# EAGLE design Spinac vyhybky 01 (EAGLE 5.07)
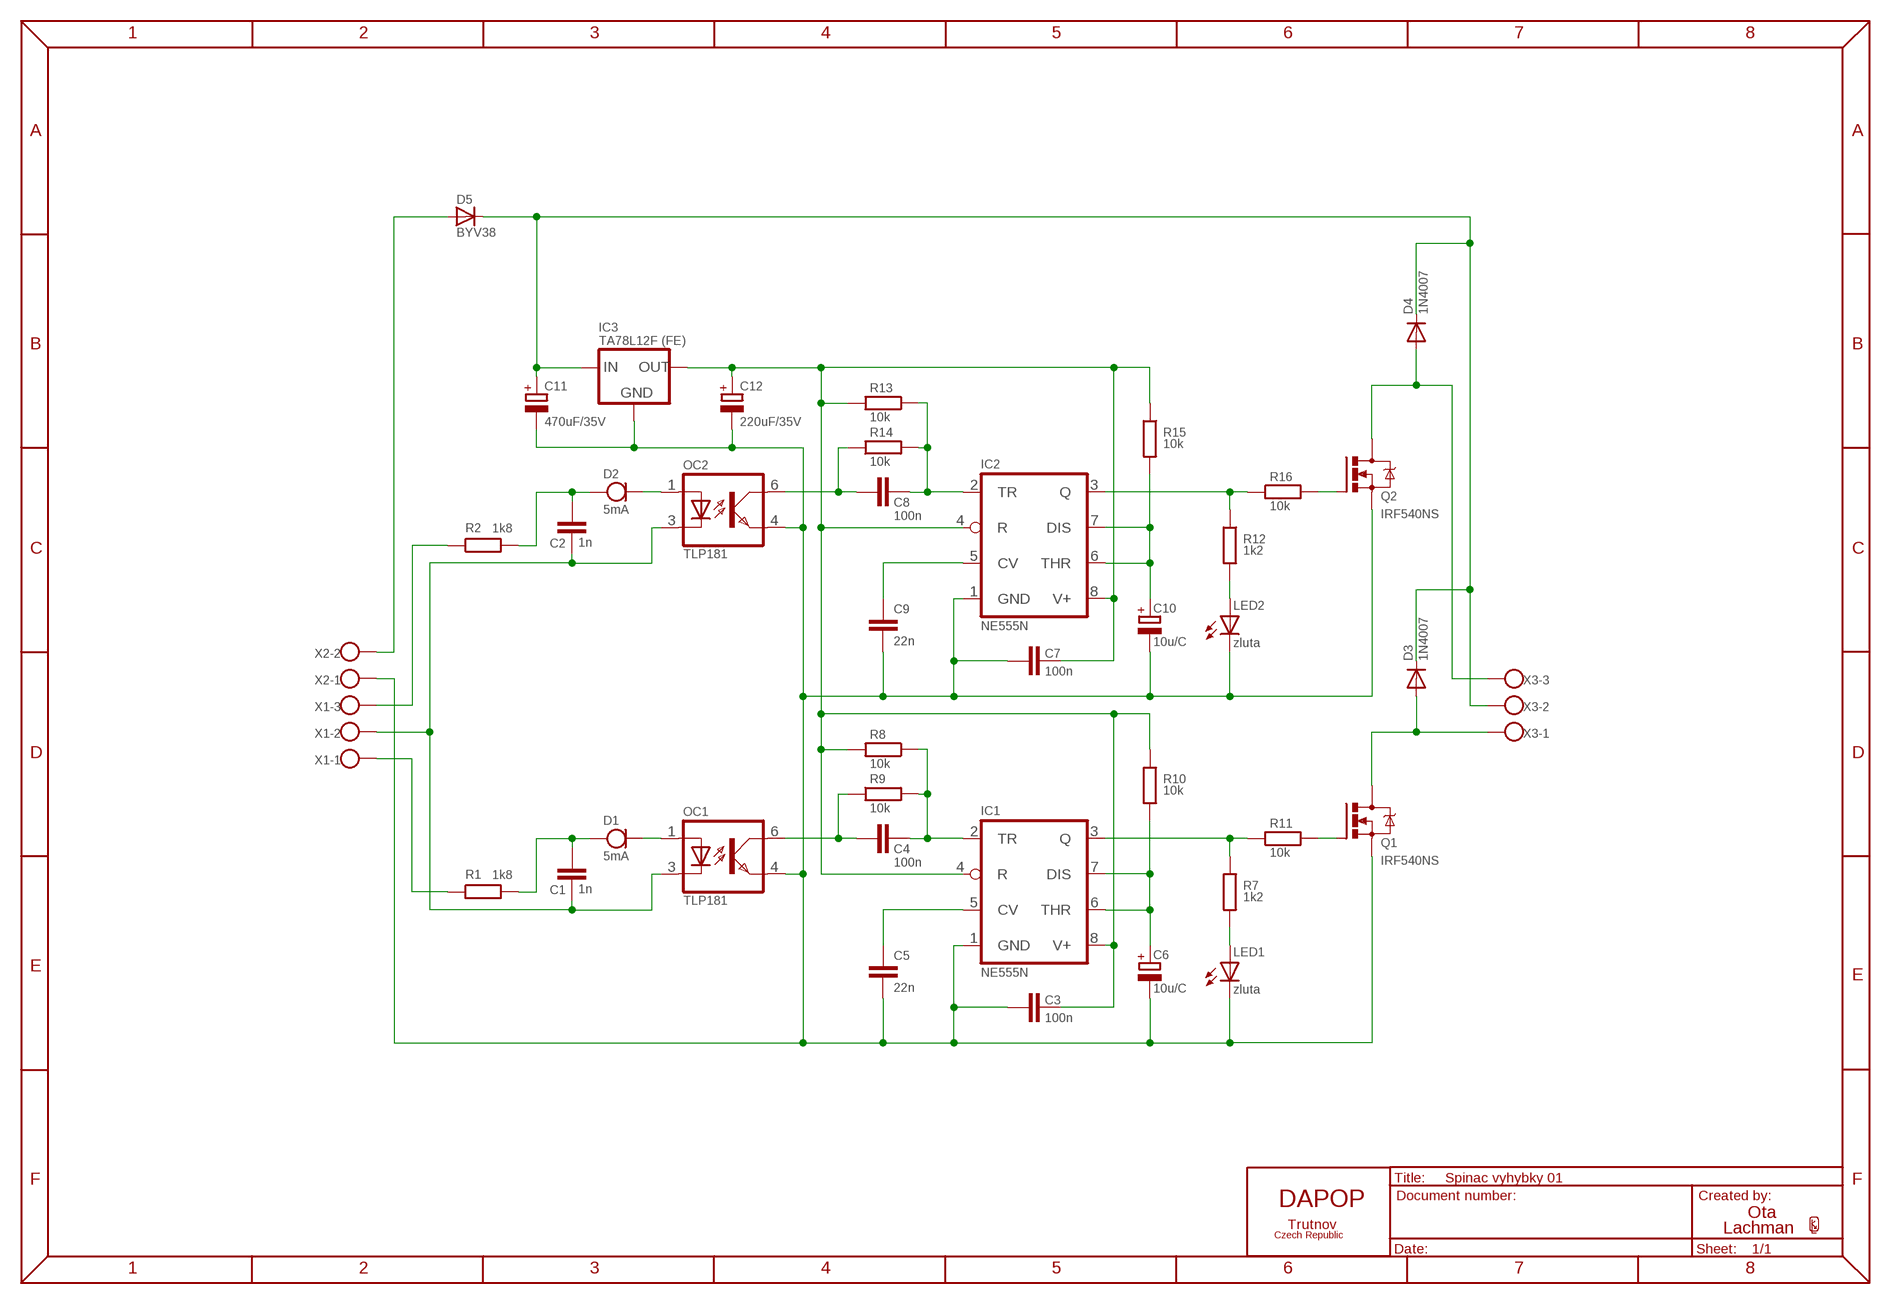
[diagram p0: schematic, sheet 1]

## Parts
C1  1n  C-EUC0805K  [C0805K]
C2  1n  C-EUC0805K  [C0805K]
C3  100n  C-EUC1206  [C1206]
C4  100n  C-EUC1206  [C1206]
C5  22n  C-EUC1206  [C1206]
C6  10u/C  CPOL-EUD/7343-31R  [D/7343-31R]
C7  100n  C-EUC1206  [C1206]
C8  100n  C-EUC1206  [C1206]
C9  22n  C-EUC1206  [C1206]
C10  10u/C  CPOL-EUD/7343-31R  [D/7343-31R]
C11  470uF/35V  CPOL-EUE5-10.5  [E5-10,5]
C12  220uF/35V  CPOL-EUE5-10.5  [E5-10,5]
D1  5mA  CRD-F  [MINIMELF]
D2  5mA  CRD-F  [MINIMELF]
D3  1N4007  DIODE-MINIMELF  [MINIMELF]
D4  1N4007  DIODE-MINIMELF  [MINIMELF]
D5  BYV38  [SOD57-10]
IC1  NE555N  [DIL08]
IC2  NE555N  [DIL08]
IC3  TA78L12F (FE)  TA78LXXF  [SOT89]
LED1  zluta  LED3MM  [LED3MM]
LED2  zluta  LED3MM  [LED3MM]
OC1  TLP181  [11-4C1]
OC2  TLP181  [11-4C1]
OL1  NAME-OL  [NAME-OL]
Q1  IRF540NS  [D2PACK]
Q2  IRF540NS  [D2PACK]
R1  1k8  R-EU_R1206  [R1206]
R2  1k8  R-EU_R1206  [R1206]
R7  1k2  R-EU_R0805  [R0805]
R8  10k  R-EU_R0805  [R0805]
R9  10k  R-EU_R0805  [R0805]
R10  10k  R-EU_R0805  [R0805]
R11  10k  R-EU_R0805  [R0805]
R12  1k2  R-EU_R0805  [R0805]
R13  10k  R-EU_R0805  [R0805]
R14  10k  R-EU_R0805  [R0805]
R15  10k  R-EU_R0805  [R0805]
R16  10k  R-EU_R0805  [R0805]
X1  AK500/3  [AK500/3]
X2  AK500/2  [AK500/2]
X3  AK500/3  [AK500/3]

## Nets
N$1: D2.C(K) OC2.1(A)
N$2: C1.2 C2.2 OC1.3(C) OC2.3(C) X1.2
N$3: C2.1 D2.A R2.2
N$4: R2.1 X1.3
N$5: C3.1 C5.2 C6.- C7.1 C9.2 C10.- C11.- C12.- IC1.1(GND) IC2.1(GND) IC3.2(GND) LED1.K(C) LED2.K(C) OC1.4(EMIT) OC2.4(EMIT) Q1.3(S) Q2.3(S) X2.1
N$6: C11.+ D3.C D4.C D5.C IC3.3(IN) X3.2
N$7: IC1.3(Q) R7.1 R11.1
N$8: LED1.A R7.2
N$9: C4.1 IC1.2(TR) R8.1 R9.2
N$10: C3.2 C7.2 C12.+ IC1.4(R) IC1.8(V+) IC2.4(R) IC2.8(V+) IC3.1(OUT) R8.2 R10.1 R13.2 R15.1
N$11: C4.2 OC1.6(COL) R9.1
N$12: C5.1 IC1.5(CV)
N$13: C6.+ IC1.6(THR) IC1.7(DIS) R10.2
N$14: D5.A X2.2
N$16: C1.1 D1.A R1.2
N$17: D1.C(K) OC1.1(A)
N$18: Q1.1(G) R11.2
N$19: IC2.3(Q) R12.1 R16.1
N$20: LED2.A R12.2
N$21: C8.1 IC2.2(TR) R13.1 R14.2
N$22: Q2.1(G) R16.2
N$23: C8.2 OC2.6(COL) R14.1
N$24: C9.1 IC2.5(CV)
N$25: C10.+ IC2.6(THR) IC2.7(DIS) R15.2
N$26: D4.A Q2.2(D) X3.3
N$27: D3.A Q1.2(D) X3.1
N$66: R1.1 X1.1

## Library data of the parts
C1-C5 C7-C9 = rcl:C-EU: CAPACITOR, European symbol
C6 C10-C12 = rcl:CPOL-EU: POLARIZED CAPACITOR, European symbol
D1 D2 = diode:CRD-F: CURRENT REGULATIVE DIODE
D3 D4 = diode:DIODE-: DIODE
D5 = diode:BYV38: DIODE
IC1 IC2 = linear:*555: TIMER
IC3 = v-reg:TA78LXXF: VOLTAGE REGULATOR
LED1 LED2 = led:LED: LED
OC1 OC2 = optocoupler:TLP181: TOSHIBA MINI FLAT OPTO COUPLER
OL1 = Names-And-Logos:NAME-OL: Name.
Q1 Q2 = transistor-power:IRF540*: HEXFET Power MOSFET
R1 R2 R7-R16 = rcl:R-EU_: RESISTOR, European symbol
X1 X3 = con-ptr500+:AK500/3: CONNECTOR
X2 = con-ptr500+:AK500/2: CONNECTOR

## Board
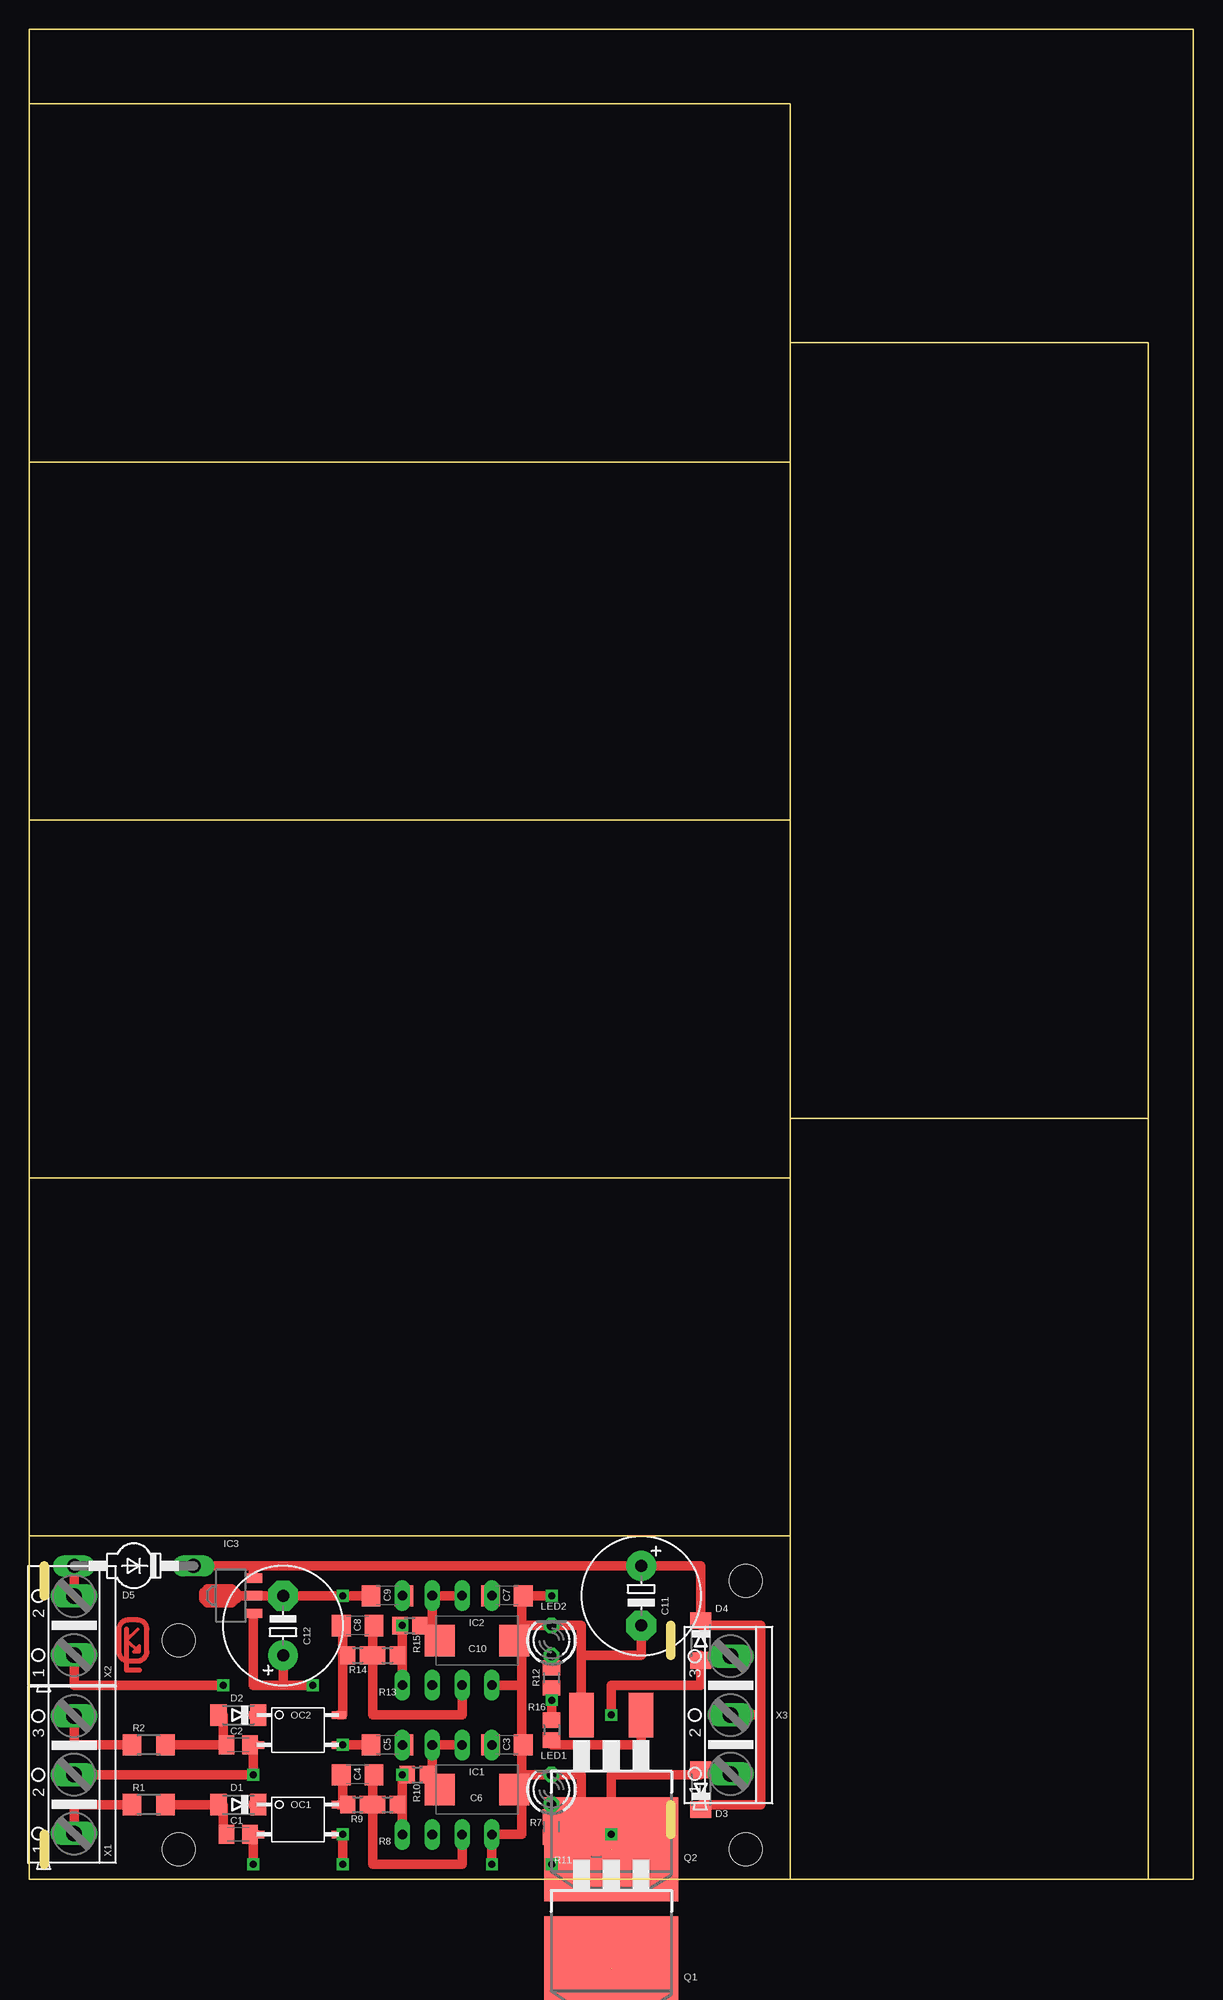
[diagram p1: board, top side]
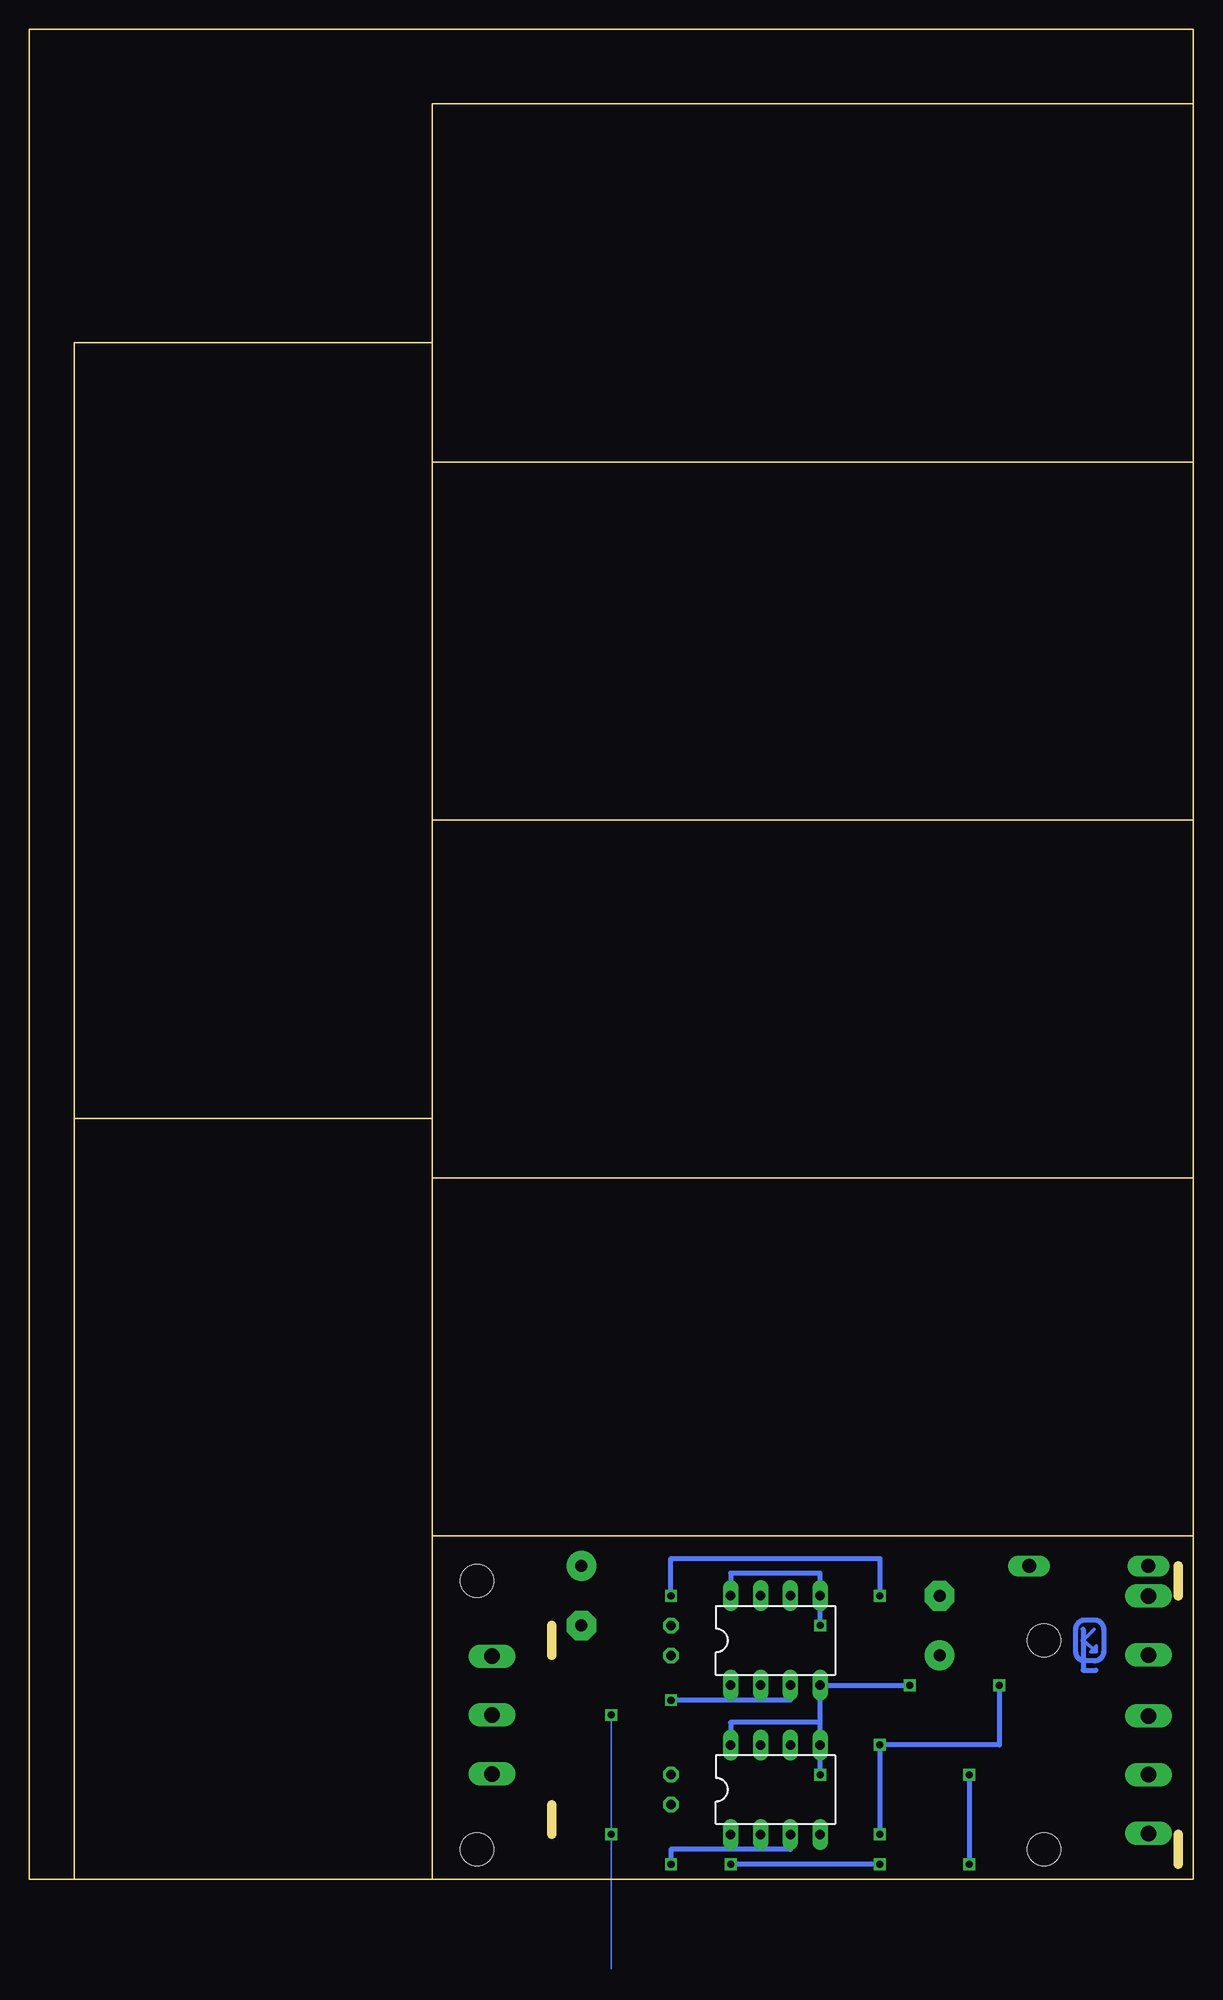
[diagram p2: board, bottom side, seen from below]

Size 99.06 x 157.48 mm. Coordinates in mm from the lower left corner, seen from the top.
Outline: 0,29.21 64.77,29.21
Outline: 64.77,29.21 64.77,0
Outline: 64.77,59.69 64.77,29.21
Outline: 0,59.69 64.77,59.69
Outline: 64.77,90.17 64.77,64.77
Outline: 64.77,64.77 64.77,59.69
Outline: 0,90.17 64.77,90.17
Outline: 64.77,120.65 64.77,90.17
Outline: 0,120.65 64.77,120.65
Outline: 64.77,130.81 64.77,151.13 0,151.13
Outline: 64.77,130.81 64.77,120.65
Outline: 64.77,64.77 95.25,64.77
Outline: 95.25,0 95.25,64.77
Outline: 95.25,64.77 95.25,130.81 64.77,130.81
Copper layers (1*16): Top 0.035mm / dielectric 1.5mm / Bottom 0.035mm
Design rules "default": minimum track width 10mil, minimum drill 24mil, track to track 8mil, track to pad 8mil, pad to pad 8mil, via to via 8mil, smd to smd 8mil, copper to edge 40mil, drill to drill 8mil, minimum pad ring 10mil, minimum via ring 8mil, stop-mask expansion 4mil, vias tented up to drill 0mil, thermal gap 10mil
Holes 2.8 mm at 12.7,2.54 60.96,2.54 60.96,25.4 12.7,20.32
Milling: 4 lines

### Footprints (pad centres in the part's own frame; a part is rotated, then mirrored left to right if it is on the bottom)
C0805K = smd 1.3 x 1.6: 1 -1,0; 2 1,0
C1206 = smd 1.6 x 1.8: 1 -1.4,0; 2 1.4,0
D/7343-31R = smd 2.55 x 2.7: + 3.175,0; - -3.175,0
E5-10,5 = drill 1.016 pad 2.54 round: + -2.54,0 | drill 1.016 pad 2.54 octagon: - 2.54,0
MINIMELF = smd 1.4 x 1.8: A 1.7,0; C -1.7,0
SOD57-10 = drill 1.194 long: A 5.08,0; C -5.08,0
DIL08 = drill 0.813 long: 1 -3.81,-3.81; 2 -1.27,-3.81; 3 1.27,-3.81; 4 3.81,-3.81; 5 3.81,3.81; 6 1.27,3.81; 7 -1.27,3.81; 8 -3.81,3.81
SOT89 = smd 0.8 x 1.4: 1 -1.499,-1.981; 2 0,-1.981; 3 1.499,-1.981
LED3MM = drill 0.813 octagon: A -1.27,0; K 1.27,0
11-4C1 = smd 1.27 x 0.635: 1 -3.493,1.27; 3 -3.493,-1.27; 4 3.493,-1.27; 6 3.493,1.27
D2PACK = smd 2.083 x 3.81: 1 -2.54,-8.89; 3 2.54,-8.89 | smd 11.43 x 8.89: 2 0,2.54
R1206 = smd 1.6 x 1.803: 1 -1.422,0; 2 1.422,0
R0805 = smd 1.3 x 1.5: 1 -0.85,0; 2 0.85,0
AK500/3 = drill 1.321 long: 1 -5.004,0; 2 0,0; 3 5.004,0
AK500/2 = drill 1.321 long: 1 -2.515,0; 2 2.515,0

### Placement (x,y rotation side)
C1  17.78,3.81 0 top
C2  17.78,11.43 0 top
C3  40.64,11.43 180 top
C4  27.94,8.89 180 top
C5  30.48,11.43 180 top
C6  38.1,7.62 180 top
C7  40.64,24.13 180 top
C8  27.94,21.59 180 top
C9  30.48,24.13 180 top
C10  38.1,20.32 180 top
C11  52.07,24.13 270 top
C12  21.59,21.59 90 top
D1  17.78,6.35 180 top
D2  17.78,13.97 180 top
D3  57.15,7.62 90 top
D4  57.15,20.32 270 top
D5  8.89,26.67 180 top
IC1  35.56,7.62 0 bottom
IC2  35.56,20.32 0 bottom
IC3  17.14,24.13 90 top
LED1  44.45,7.62 90 top
LED2  44.45,20.32 90 top
OC1  22.86,5.08 0 top
OC2  22.86,12.7 0 top
OL1  8.89,20.32 0 top
Q1  49.53,-5.08 180 top
Q2  49.53,5.08 180 top
R1  10.16,6.35 0 top
R2  10.16,11.43 0 top
R7  44.45,4.45 90 top
R8  30.48,6.35 0 top
R9  27.94,6.35 0 top
R10  33.02,8.89 0 top
R11  48.26,1.27 0 top
R12  44.45,17.14 90 top
R13  30.48,19.05 0 top
R14  27.94,19.05 0 top
R15  32.38,21.59 0 top
R16  44.45,12.7 270 top
U$2  [PAD02TOP]  99.06,0 90 top
X1  3.81,8.89 90 top
X2  3.81,21.59 90 top
X3  59.69,13.97 90 top

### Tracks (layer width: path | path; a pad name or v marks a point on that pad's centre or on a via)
N$1
  Top 0.813: D2.C OC2.1 19.05,13.97
N$2  (via drill 0.6)
  Top 0.813: 19.05,3.81 C1.2 | v19.05,1.27 19.05,3.81 | 19.05,3.81 OC1.3 | 19.05,11.43 v19.05,8.89 X1.2 | 19.05,11.43 C2.2 | 19.05,11.43 OC2.3
  Bottom 0.406: v19.05,8.89 v19.05,1.27
N$3
  Top 0.813: D2.A 16.51,13.97 16.51,11.43 | 16.51,11.43 C2.1 | R2.2 16.51,11.43
N$4
  Top 0.813: R2.1 3.81,11.43 3.81,13.97
N$5  (via drill 0.6)
  Top 0.813: v16.51,16.51 3.81,16.51 X2.1 | 16.51,24.13 IC3.2 C12.- v26.67,24.13 C9.2 29.21,24.13 | 46.99,19.05 Q2.3 | OC1.4 v26.67,3.81 v26.67,1.27 | OC2.4 v26.67,11.43 C5.2 29.21,11.43 | 41.91,7.62 41.91,3.81 IC1.1 v39.37,1.27 | 41.91,7.62 C6.- | 41.91,7.62 41.91,8.89 | 41.91,8.89 LED1.K 46.99,8.89 Q1.3 | 46.99,19.05 46.99,21.59 LED2.K 41.91,21.59 | 41.91,11.43 C3.1 | 41.91,8.89 41.91,11.43 | 41.91,11.43 41.91,16.51 | 41.91,16.51 IC2.1 | 41.91,16.51 41.91,20.32 | 41.91,20.32 C10.- | 41.91,21.59 41.91,24.13 C7.1 v44.45,24.13 | 41.91,20.32 41.91,21.59 | C11.- 52.07,19.05 46.99,19.05
  Bottom 0.406: v44.45,24.13 44.45,27.3 26.67,27.3 v26.67,24.13 | v16.51,16.51 16.51,11.43 v26.67,11.43 v26.67,3.81 | v26.67,1.27 v39.37,1.27
N$6
  Top 0.406: 19.05,26.04 19.05,25.63
  Top 0.813: 19.05,26.67 19.05,26.04 19.05,25.63 IC3.3 | 19.05,26.67 C11.+ 57.15,26.67 D4.C 57.15,21.59 62.23,21.59 62.23,13.97 | 62.23,13.97 X3.2 | 62.23,13.97 62.23,6.35 57.15,6.35 D3.C | D5.C 19.05,26.67
N$7  (via drill 0.6)
  Top 0.406: v44.45,1.27 44.45,3.81
  Top 0.813: 44.45,3.81 R7.1 v44.45,1.27 R11.1
  Bottom 0.406: IC1.3 34.29,2.54 44.45,2.54 v44.45,1.27
N$8
  Top 0.406: 44.45,5.08 R7.2 LED1.A
N$9
  Top 0.813: C4.1 29.21,8.89 29.21,6.35 | 29.21,6.35 R8.1 | IC1.2 36.83,1.27 29.21,1.27 29.21,6.35 | 29.21,6.35 R9.2
N$10  (via drill 0.6)
  Top 0.406: 38.73,11.43 C3.2 IC1.8 | IC2.8 C7.2 | IC3.1 19.05,22.63 19.05,22.23
  Top 0.813: 19.05,22.23 19.05,16.51 21.59,16.51 | v24.13,16.51 21.59,16.51 | IC2.4 31.75,19.05 | R15.1 v31.75,21.59 31.75,19.05 | 31.75,19.05 R13.2 | IC1.4 31.75,6.35 | 31.75,6.35 R8.2 | 31.75,6.35 v31.75,8.89 R10.1 | 21.59,16.51 C12.+
  Bottom 0.406: v24.13,16.51 IC2.4 31.75,13.34 | v31.75,8.89 31.75,13.34 | IC1.8 39.37,13.34 31.75,13.34 | v31.75,21.59 31.75,26.04 39.37,26.04 IC2.8
  other vias: 39.37,11.43
N$11
  Top 0.813: OC1.6 R9.1 26.67,6.35 26.67,8.89 C4.2
N$12
  Top 0.406: C5.1 IC1.5
N$13
  Top 0.813: C6.+ 34.29,7.62 34.29,8.89 | 34.29,8.89 R10.2 | 34.29,8.89 IC1.6 IC1.7
N$14
  Top 0.813: X2.2 D5.A
N$16
  Top 0.813: C1.1 16.51,3.81 16.51,6.35 D1.A R1.2
N$17
  Top 0.813: D1.C OC1.1 19.05,6.35
N$18
  Top 0.813: R11.2 52.07,1.27 Q1.1
N$19  (via drill 0.6)
  Top 0.406: v44.45,15.24 44.45,16.51
  Top 0.813: 44.45,16.51 R12.1 v44.45,15.24 R16.1
  Bottom 0.406: IC2.3 34.29,15.24 v44.45,15.24
N$20
  Top 0.406: 44.45,17.78 R12.2 LED2.A
N$21
  Top 0.813: 29.21,19.05 R14.2 | C8.1 29.21,21.59 29.21,19.05 | 29.84,19.05 R13.1 29.21,19.05 | IC2.2 36.83,13.97 29.21,13.97 29.21,19.05
N$22
  Top 0.813: R16.2 44.45,11.43 52.07,11.43 Q2.1
N$23
  Top 0.813: OC2.6 26.67,13.97 26.67,19.05 | C8.2 26.67,21.59 26.67,19.05 | 26.67,19.05 R14.1
N$24
  Top 0.406: C9.1 IC2.5
N$25
  Top 0.813: IC2.7 IC2.6 34.29,21.59 | 34.29,21.59 R15.2 | C10.+ 34.29,20.32 34.29,21.59
N$26  (via drill 0.6)  (1 unrouted)
  Top 0.813: 57.15,19.05 D4.A | X3.3 57.15,18.97 57.15,19.05 | 57.15,19.05 57.15,16.51 49.53,16.51 v49.53,13.97
  Bottom 0.127: Q2.2 v49.53,13.97
N$27  (via drill 0.6)  (1 unrouted)
  Top 0.813: 57.15,8.97 D3.A 57.15,8.89 | 57.15,8.97 X3.1 | 57.15,8.89 57.15,8.97 | 57.15,8.89 49.53,8.89 v49.53,3.81
  Bottom 0.127: Q1.2 v49.53,3.81
N$66
  Top 0.813: R1.1 3.81,6.35 3.81,3.81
